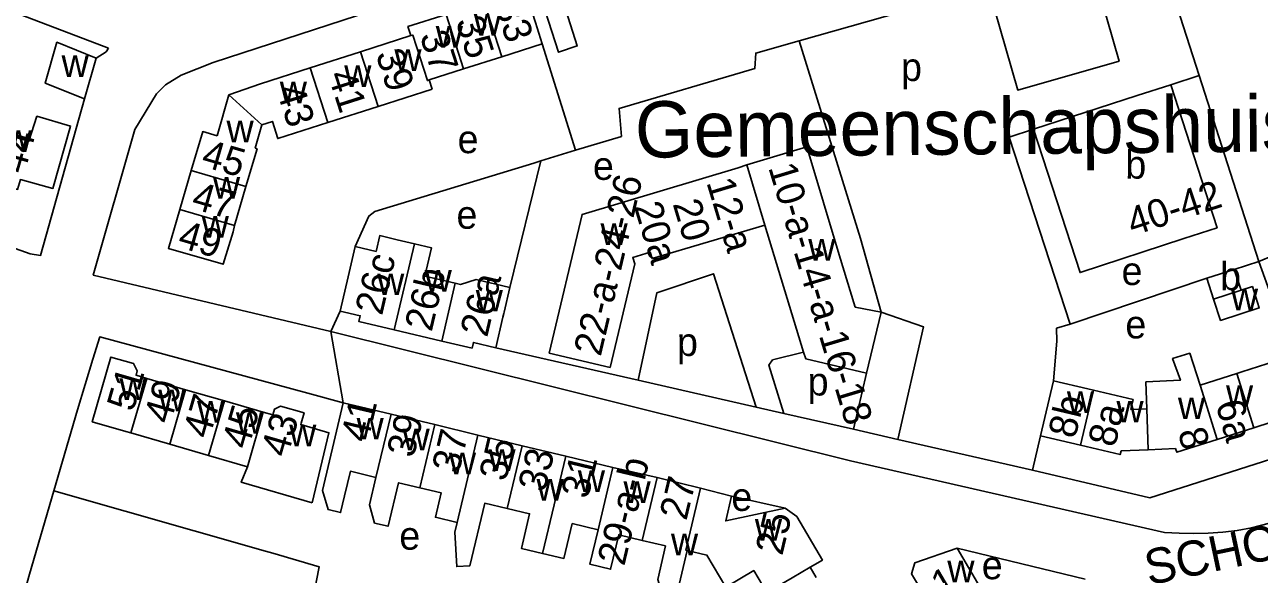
# Model space of a CAD drawing. Extents: x 159261 to 160849, y 382514 to 384534.
# Drawn here: x 160007.7 to 160183.5, y 383463.4 to 383541.7 of the extents above; entities that cross this region are included whole.
import ezdxf

# ---------------------------------------------------------------- set-up
doc = ezdxf.new("R2010")
doc.units = 0
for name, color, linetype in [('BLT_Basislijn', 7, 'Continuous'), ('BLT_Bebouwing', 7, 'Continuous'), ('BLT_Bebouwing_beschrifting', 7, 'Continuous'), ('BLT_Centroide', 7, 'Continuous'), ('BLT_Huisnummer', 7, 'Continuous'), ('BLT_Huisnummer_ tussenligend', 7, 'Continuous'), ('BLT_Huisnummer_reeks', 7, 'Continuous'), ('BLT_Onderverdeling_panden', 7, 'Continuous'), ('BLT_Straatnaam', 7, 'Continuous'), ('BLT_Vlakafsluiter', 7, 'Continuous')]:
    doc.layers.add(name, color=color, linetype=linetype)

msp = doc.modelspace()

# ---------------------------------------------------------------- linework, layer by layer
at = {"layer": 'BLT_Basislijn'}
for p, q in [((160168.63, 383553.87), (160174.89, 383534.41)), ((160117.97, 383539.35), (160144.85, 383547.05)), ((160081.41, 383538.94), (160086.13, 383523.77)), ((160117.97, 383539.35), (160126.71, 383511.19)), ((160019.32, 383537.77), (160019.68, 383538.31)), ((160170.86, 383533.1), (160174.89, 383534.41)), ((160174.89, 383534.41), (160183.4, 383507.92)), ((160081.19, 383522.24), (160086.13, 383523.77)), ((160076.8, 383504.22), (160081.19, 383522.24)), ((160129.62, 383500.69), (160126.71, 383511.19)), ((160179.9, 383506.79), (160183.4, 383507.92)), ((160183.4, 383507.92), (160192.57, 383482.25)), ((160156.52, 383498.99), (160176.01, 383505.53)), ((160154.58, 383498.41), (160156.52, 383498.99)), ((160074.79, 383495.65), (160095.05, 383491.03)), ((160127.56, 383492.03), (160125.7, 383484.03)), ((160095.05, 383491.03), (160111.84, 383487.2)), ((160053.08, 383487.81), (160048.04, 383489.17)), ((160111.84, 383487.2), (160115.77, 383486.3)), ((160115.77, 383486.3), (160125.7, 383484.03)), ((160125.7, 383484.03), (160132.03, 383482.59)), ((160132.03, 383482.59), (160151.16, 383478.22)), ((160151.16, 383478.22), (160152.32, 383483.09)), ((160189.73, 383481.26), (160167.88, 383474.28)), ((160169.97, 383469.34), (160125.26, 383479.54)), ((160151.16, 383478.22), (160167.88, 383474.28)), ((160042.01, 383466.69), (160011.91, 383475.28)), ((160108.36, 383474.52), (160115.99, 383472.79)), ((160182.34, 383470), (160192, 383472.48)), ((160140.45, 383467.1), (160158.69, 383462.67)), ((160119.53, 383464.37), (160120.4, 383462.9))]:
    msp.add_line(p, q, dxfattribs=at)
for points in [[(159935.34, 383566.83), (159950.74, 383571.9), (159950.72, 383570.15), (160006.11, 383549.4), (160004.08, 383544.22), (160019.68, 383538.31)], [(160144.85, 383547.05), (160149.07, 383532.33), (160163.5, 383536.46), (160159.28, 383551.19)], [(160051.3, 383497.97), (160017.51, 383505.98), (160023.43, 383526.72), (160026.52, 383531.81), (160027.8, 383533.09), (160030.02, 383534.48), (160034.57, 383536.26), (160077.68, 383550.38)], [(160117.97, 383539.35), (160111.79, 383537.61), (160111.64, 383535.41), (160092.34, 383529.73), (160092.68, 383525.75), (160086.13, 383523.77)], [(160019.32, 383537.77), (160017.92, 383536.89)], [(160016.26, 383531.1), (160010.01, 383508.78), (160008.53, 383509.02), (159995, 383513.79), (159988.8, 383517.76), (159987.45, 383518.5), (159962.86, 383526.95)], [(160156.52, 383498.99), (160147.88, 383525.65), (160151.33, 383526.77)], [(160054.78, 383510.05), (160056.7, 383514.4), (160057.58, 383515.06), (160080.2, 383521.93), (160081.19, 383522.24)], [(160095.05, 383491.03), (160097.72, 383503.48), (160105.76, 383506.17), (160111.84, 383487.2)], [(160052.63, 383500.87), (160051.3, 383497.97)], [(160129.62, 383500.69), (160135.66, 383498.63), (160132.03, 383482.59)], [(160154.17, 383490.94), (160154.66, 383496.59), (160154.58, 383498.41)], [(160017.45, 383494.01), (160018.42, 383497.18), (160048.04, 383489.17)], [(160125.26, 383479.54), (160051.3, 383497.97)], [(160118.6, 383495.03), (160114.18, 383493.92), (160113.64, 383493.18), (160115.77, 383486.3)], [(160011.91, 383475.28), (160015.28, 383486.79), (160017.45, 383494.01)], [(160011.91, 383475.28), (160008.45, 383463.41), (160006.23, 383455.63), (160006.03, 383454.89)], [(160182.34, 383470), (160180.31, 383469.63), (160178.25, 383469.37), (160176.18, 383469.21), (160174.11, 383469.17), (160172.04, 383469.24), (160169.97, 383469.34)], [(160072.06, 383454.77), (160048.95, 383460.77), (160049.67, 383464.43), (160043.07, 383466.39), (160042.01, 383466.69)]]:
    msp.add_lwpolyline(points, dxfattribs=at)
at = {"layer": 'BLT_Bebouwing'}
for p, q in [((160062.7, 383540.09), (160055.53, 383537.8)), ((160075.63, 383537.09), (160081.41, 383538.94)), ((160016.26, 383531.1), (160017.92, 383536.89)), ((160055.53, 383537.8), (160048.39, 383535.51)), ((160070.2, 383535.35), (160075.63, 383537.09)), ((160065.33, 383533.79), (160070.2, 383535.35)), ((160065.33, 383533.79), (160065.75, 383532.48)), ((160058.05, 383530.02), (160065.75, 383532.48)), ((160050.91, 383527.73), (160058.05, 383530.02)), ((160031.45, 383520.88), (160029.82, 383515.33)), ((160037.61, 383513.05), (160039.23, 383518.59)), ((160123.67, 383508.88), (160121.42, 383516.35)), ((160113.08, 383513.11), (160118.6, 383495.03)), ((160125.92, 383501.41), (160123.67, 383508.88)), ((160176.01, 383505.53), (160179.9, 383506.79)), ((160176.96, 383502.57), (160176.01, 383505.53)), ((160179.9, 383506.79), (160180.86, 383503.83)), ((160129.62, 383500.69), (160127.56, 383492.03)), ((160067.09, 383496.6), (160060.32, 383498.18)), ((160071.41, 383495.58), (160067.09, 383496.6)), ((160030.64, 383489.67), (160025.12, 383491.28)), ((160180.27, 383491.96), (160175.02, 383490.29)), ((160036.17, 383488.07), (160030.64, 383489.67)), ((160152.32, 383483.09), (160154.17, 383490.94)), ((160167.3, 383490.81), (160167.44, 383486.95)), ((160041.69, 383486.47), (160036.17, 383488.07)), ((160053.08, 383487.81), (160059.88, 383486.17)), ((160059.88, 383486.17), (160066.14, 383484.7)), ((160167.44, 383486.95), (160165.16, 383486.85)), ((160188.2, 383486.02), (160182.66, 383484.25)), ((160066.14, 383484.7), (160072.24, 383483.2)), ((160182.66, 383484.25), (160177.48, 383482.59)), ((160022.87, 383483.5), (160028.39, 383481.9)), ((160072.24, 383483.2), (160078.55, 383481.69)), ((160157.99, 383481.75), (160152.32, 383483.09)), ((160028.39, 383481.9), (160033.91, 383480.3)), ((160078.55, 383481.69), (160084.76, 383480.2)), ((160167.66, 383481.11), (160163.78, 383480.94)), ((160171.54, 383481.28), (160167.66, 383481.11)), ((160033.91, 383480.3), (160039.44, 383478.7)), ((160084.76, 383480.2), (160091.46, 383478.59)), ((160091.46, 383478.59), (160097.77, 383477.17)), ((160097.77, 383477.17), (160103.92, 383475.64)), ((160103.92, 383475.64), (160108.36, 383474.52)), ((160144.16, 383460.78), (160140.45, 383467.1))]:
    msp.add_line(p, q, dxfattribs=at)
for points in [[(160089.22, 383545.16), (160084.76, 383543.73), (160086.39, 383538.63), (160083.74, 383537.72), (160080.45, 383547.94), (160082.75, 383548.67), (160081.75, 383551.8)], [(160081.41, 383538.94), (160080.45, 383541.94), (160078.92, 383546.71)], [(160067.72, 383543.12), (160062.29, 383541.38), (160062.7, 383540.09)], [(160017.92, 383536.89), (160012.34, 383539.16), (160010.67, 383533.32), (160016.26, 383531.1)], [(160048.39, 383535.51), (160041.32, 383533.24), (160036.8, 383531.64)], [(160036.8, 383531.64), (160035.12, 383525.83)], [(160151.33, 383526.77), (160166.1, 383531.56), (160170.86, 383533.1)], [(160170.86, 383533.1), (160177.46, 383512.73), (160172.71, 383511.18)], [(160035.12, 383525.83), (160033.08, 383526.42), (160031.45, 383520.88)], [(160040.53, 383524.06), (160041.5, 383527.4)], [(160041.5, 383527.4), (160042.99, 383527.87), (160043.77, 383525.44), (160050.91, 383527.73)], [(160172.71, 383511.18), (160157.95, 383506.35), (160151.33, 383526.77)], [(160039.23, 383518.59), (160040.81, 383523.97), (160040.53, 383524.06)], [(160110.5, 383521.67), (160115.29, 383523.11), (160119.05, 383524.24), (160121.42, 383516.35)], [(160110.5, 383521.67), (160109.3, 383521.27), (160087.07, 383514.64), (160082.41, 383494.87), (160091.08, 383492.83)], [(160029.82, 383515.33), (160028.19, 383509.79), (160035.99, 383507.53), (160037.4, 383512.14), (160037.61, 383513.05)], [(160091.08, 383492.83), (160094.56, 383507.61), (160094.29, 383508.51), (160096.77, 383509.24), (160097.04, 383508.33), (160113.08, 383513.11)], [(160063.2, 383510.46), (160060.77, 383511.02), (160058.28, 383511.61), (160057.76, 383509.35), (160054.78, 383510.05)], [(160054.78, 383510.05), (160053.77, 383505.74), (160052.63, 383500.87)], [(160069.02, 383504.83), (160064.68, 383505.85), (160065.62, 383509.89), (160063.2, 383510.46)], [(160076.8, 383504.22), (160072.01, 383505.34), (160069.76, 383504.66), (160069.02, 383504.83)], [(160076.8, 383504.22), (160075.98, 383500.73), (160075.93, 383500.52), (160075.81, 383500), (160074.79, 383495.65)], [(160180.86, 383503.83), (160182.48, 383504.35), (160183.46, 383501.31), (160177.94, 383499.53), (160176.96, 383502.57)], [(160052.63, 383500.87), (160053.24, 383500.73), (160055.5, 383500.2), (160055.45, 383500), (160055.3, 383499.36), (160060.32, 383498.18)], [(160125.92, 383501.41), (160129.62, 383500.69)], [(160074.79, 383495.65), (160071.6, 383496.4), (160071.41, 383495.58)], [(160127.56, 383492.03), (160118.9, 383494.08), (160118.6, 383495.03)], [(160175.02, 383490.29), (160173.56, 383494.86), (160171.12, 383494.09), (160172.23, 383491.02), (160167.3, 383490.81)], [(160025.12, 383491.28), (160023.59, 383491.72), (160023.77, 383492.34), (160023.24, 383493.38), (160020.01, 383494.32), (160017.35, 383485.1), (160022.15, 383483.71), (160022.87, 383483.5)], [(160185.74, 383493.71), (160180.98, 383492.19), (160180.27, 383491.96)], [(160154.17, 383490.94), (160159.04, 383489.79), (160159.84, 383489.6)], [(160165.16, 383486.85), (160165.5, 383488.27), (160159.84, 383489.6)], [(160053.08, 383487.81), (160051.92, 383482.94), (160050.11, 383475.32), (160050.92, 383472.59), (160052.71, 383472.16), (160053.27, 383474.56), (160054.1, 383478.04), (160057.73, 383477.17)], [(160047.09, 383484.91), (160047.51, 383486.35), (160044.17, 383487.31), (160043.3, 383486.91), (160043.06, 383486.08), (160041.69, 383486.47)], [(160048.65, 383473.57), (160051.05, 383483.53), (160047.03, 383484.7), (160047.09, 383484.91)], [(160177.48, 383482.59), (160171.71, 383480.75), (160171.54, 383481.28)], [(160163.78, 383480.94), (160163.65, 383480.42), (160157.99, 383481.75)], [(160039.44, 383478.7), (160038.56, 383476.49), (160048.65, 383473.57)], [(160057.73, 383477.17), (160056.81, 383473.28), (160057.53, 383470.68), (160059.47, 383470.21), (160060.95, 383476.41), (160063.99, 383475.69)], [(160063.99, 383475.69), (160067.03, 383474.97), (160066.2, 383471.49), (160069.28, 383470.75)], [(160108.36, 383474.52), (160107.52, 383470.97), (160115.99, 383472.79)], [(160069.28, 383470.75), (160068.96, 383469.39), (160069.23, 383464.48), (160071.11, 383464.59), (160073.23, 383473.5), (160076.42, 383472.74)], [(160076.42, 383472.74), (160079.61, 383471.99), (160078.44, 383467.07), (160081.46, 383466.35)], [(160115.99, 383472.79), (160117.66, 383471.59), (160121.29, 383465.41), (160119.53, 383464.37)], [(160081.46, 383466.35), (160084.49, 383465.63), (160085.67, 383470.59), (160089.35, 383469.72)], [(160089.35, 383469.72), (160088.18, 383464.81), (160091.13, 383464.1), (160092.3, 383469.01), (160095.61, 383468.21)], [(160095.61, 383468.21), (160098.93, 383467.41), (160097.85, 383462.62), (160098.22, 383461.42), (160095.27, 383460.49), (160096.83, 383455.5), (160099.6, 383455.86), (160101.31, 383452.17)], [(160103.95, 383453.71), (160102.27, 383457.2), (160100.89, 383461.9), (160102.05, 383466.78)], [(160102.05, 383466.78), (160104.84, 383466.11), (160107.52, 383461.56), (160111.51, 383463.91), (160113.36, 383460.76), (160116.98, 383462.87), (160119.53, 383464.37)], [(160140.45, 383467.1), (160134.45, 383465.03), (160133.97, 383463.43), (160137.8, 383457.05)]]:
    msp.add_lwpolyline(points, dxfattribs=at)
msp.add_lwpolyline([(159997.89, 383528.09), (160001.91, 383526.92), (160002.25, 383528.07), (160003.24, 383528.61), (160005.33, 383528), (160005.85, 383527.02), (160005.51, 383525.86), (160008.34, 383525.04), (160009.48, 383528.62), (160014.28, 383527.22), (160011.76, 383518.33), (160007.14, 383519.6), (160006.73, 383518.19), (159999.59, 383520.24), (159999.37, 383519.43), (159996.66, 383520.21), (159996.89, 383521.02), (159995.94, 383521.27)], close=True, dxfattribs=at)
at = {"layer": 'BLT_Onderverdeling_panden'}
for p, q in [((160073.15, 383544.86), (160075.63, 383537.09)), ((160067.72, 383543.12), (160070.2, 383535.35)), ((160058.05, 383530.02), (160055.53, 383537.8)), ((160050.91, 383527.73), (160048.39, 383535.51)), ((160036.8, 383531.64), (160041.5, 383527.4)), ((160113.08, 383513.11), (160110.5, 383521.67)), ((160031.45, 383520.88), (160039.23, 383518.59)), ((160029.82, 383515.33), (160037.61, 383513.05)), ((160063.2, 383510.46), (160060.32, 383498.18)), ((160069.02, 383504.83), (160067.09, 383496.6)), ((160176.96, 383502.57), (160180.86, 383503.83)), ((160025.12, 383491.28), (160022.87, 383483.5)), ((160180.27, 383491.96), (160182.66, 383484.25)), ((160030.64, 383489.67), (160028.39, 383481.9)), ((160157.99, 383481.75), (160159.84, 383489.6)), ((160175.02, 383490.29), (160177.48, 383482.59)), ((160036.17, 383488.07), (160033.91, 383480.3)), ((160041.69, 383486.47), (160039.44, 383478.7)), ((160057.73, 383477.17), (160059.88, 383486.17)), ((160167.44, 383486.95), (160167.66, 383481.11)), ((160063.99, 383475.69), (160066.14, 383484.7)), ((160069.28, 383470.75), (160072.24, 383483.2)), ((160076.42, 383472.74), (160078.55, 383481.69)), ((160081.46, 383466.35), (160084.76, 383480.2)), ((160089.35, 383469.72), (160091.46, 383478.59)), ((160095.61, 383468.21), (160097.77, 383477.17))]:
    msp.add_line(p, q, dxfattribs=at)
for points in [[(160062.7, 383540.09), (160062.98, 383540.18), (160065.05, 383533.7), (160065.33, 383533.79)], [(160103.92, 383475.64), (160101.82, 383466.83), (160102.05, 383466.78)]]:
    msp.add_lwpolyline(points, dxfattribs=at)
at = {"layer": 'BLT_Vlakafsluiter'}
for p, q in [((160183.4, 383507.92), (160193.22, 383512.08)), ((160051.3, 383497.97), (160053.08, 383487.81))]:
    msp.add_line(p, q, dxfattribs=at)

# ---------------------------------------------------------------- texts
at = {"layer": 'BLT_Bebouwing_beschrifting'}
msp.add_text('Gemeenschapshuis', height=8, rotation=0.5505, dxfattribs=at).set_placement((160094.62, 383522.71))
at = {"layer": 'BLT_Centroide'}
for s, p in [('w', (160071.67, 383540.09)), ('w', (160066.25, 383538.38)), ('w', (160012.99, 383534.2)), ('w', (160060.36, 383535.05)), ('w', (160053.22, 383532.77)), ('p', (160132.47, 383533.63)), ('w', (160044.05, 383530.47)), ('w', (160004.91, 383523.53)), ('w', (160036.47, 383524.89)), ('e', (160069.36, 383523.35)), ('b', (160164.39, 383519.73)), ('e', (160088.62, 383519.55)), ('w', (160034.54, 383516.88)), ('w', (160032.93, 383511.31)), ('e', (160069.2, 383512.59)), ('w', (160089.7, 383510.27)), ('w', (160119.26, 383508.06)), ('e', (160163.86, 383504.57)), ('b', (160177.89, 383503.84)), ('w', (160057.91, 383503.14)), ('w', (160064.67, 383503.64)), ('w', (160071.94, 383500.81)), ('w', (160179.42, 383500.97)), ('e', (160164.4, 383496.97)), ('p', (160100.58, 383494.47)), ('w', (160021.23, 383488.19)), ('p', (160119.18, 383488.84)), ('w', (160026.75, 383486.59)), ('w', (160156.08, 383486.34)), ('w', (160178.72, 383487.23)), ('w', (160032.28, 383484.98)), ('w', (160163.13, 383485)), ('w', (160171.88, 383485.47)), ('w', (160037.8, 383483.39)), ('w', (160045.39, 383481.62)), ('w', (160054.98, 383482.58)), ('w', (160061.52, 383481.03)), ('w', (160068.11, 383477.61)), ('w', (160073.75, 383478.11)), ('w', (160086.47, 383475.09)), ('w', (160080.59, 383473.88)), ('w', (160092.97, 383473.53)), ('e', (160108.32, 383472.4)), ('w', (160111.67, 383468.16)), ('e', (160061.06, 383466.88)), ('w', (160099.72, 383466.09)), ('w', (160139.06, 383462.23)), ('e', (160143.96, 383462.67))]:
    msp.add_text(s, height=4, dxfattribs=at).set_placement(p)
at = {"layer": 'BLT_Huisnummer'}
for s, rotation, p in [('33', 287.7637, (160074.6, 383544.49)), ('39', 287.7636, (160057.67, 383537.48)), ('43', 287.7614, (160043.51, 383532.42)), ('44', 74.1719, (160007.67, 383520.26)), ('45', 343.9128, (160032.71, 383521.55)), ('49', 343.9044, (160029.36, 383510.02)), ('26c', 76.8035, (160058.6, 383500.12)), ('26b', 76.7967, (160065.66, 383497.8)), ('26a', 76.7977, (160073.56, 383497.01)), ('51', 73.8406, (160023.18, 383486.4)), ('47', 73.8406, (160034.02, 383482.54)), ('41', 76.6284, (160056.56, 383482.02)), ('8b', 76.7269, (160157.25, 383482.57)), ('6a', 285.893, (160177.21, 383487.65)), ('43', 73.8342, (160045.12, 383479.89)), ('39', 76.6284, (160063.1, 383479.85)), ('8a', 76.8108, (160162.92, 383481.34)), ('8', 285.893, (160171.83, 383483.66)), ('35', 76.6275, (160076.23, 383476.49)), ('31', 76.4221, (160087.9, 383474)), ('27', 76.6417, (160101.92, 383470.91)), ('25', 76.6417, (160115.56, 383465.92)), ('1', 30.3953, (160138.28, 383459.76))]:
    msp.add_text(s, height=4, rotation=rotation, dxfattribs=at).set_placement(p)
at = {"layer": 'BLT_Huisnummer_ tussenligend'}
for s, rotation, p in [('35', 287.7637, (160069.04, 383542.17)), ('37', 287.7637, (160063.94, 383540.1)), ('41', 287.7636, (160050.86, 383534.49)), ('47', 343.9128, (160031.31, 383515.54)), ('49', 73.8406, (160028.47, 383484.64)), ('45', 73.8342, (160039.56, 383481.04)), ('37', 76.6275, (160069.52, 383477.63)), ('33', 76.4221, (160081.78, 383474.95))]:
    msp.add_text(s, height=4, rotation=rotation, dxfattribs=at).set_placement(p)
at = {"layer": 'BLT_Huisnummer_reeks'}
for s, rotation, p in [('10-a-14-a-16-18', 286.7638, (160113.55, 383521.33)), ('22-a-24-26', 76.7474, (160089.72, 383494.29)), ('12-a', 286.7638, (160104.74, 383519.21)), ('40-42', 18.1046, (160165.44, 383511.54)), ('20a', 286.7638, (160094.42, 383515.8)), ('20', 286.7638, (160099.94, 383516.15)), ('29-a-b', 76.6417, (160093.08, 383464.45))]:
    msp.add_text(s, height=4, rotation=rotation, dxfattribs=at).set_placement(p)
at = {"layer": 'BLT_Straatnaam'}
msp.add_text('SCHOUWBROEKSEWEG', height=5, rotation=11.9132, dxfattribs=at).set_placement((160167.73, 383461.79))

doc.saveas('drawing.dxf')
